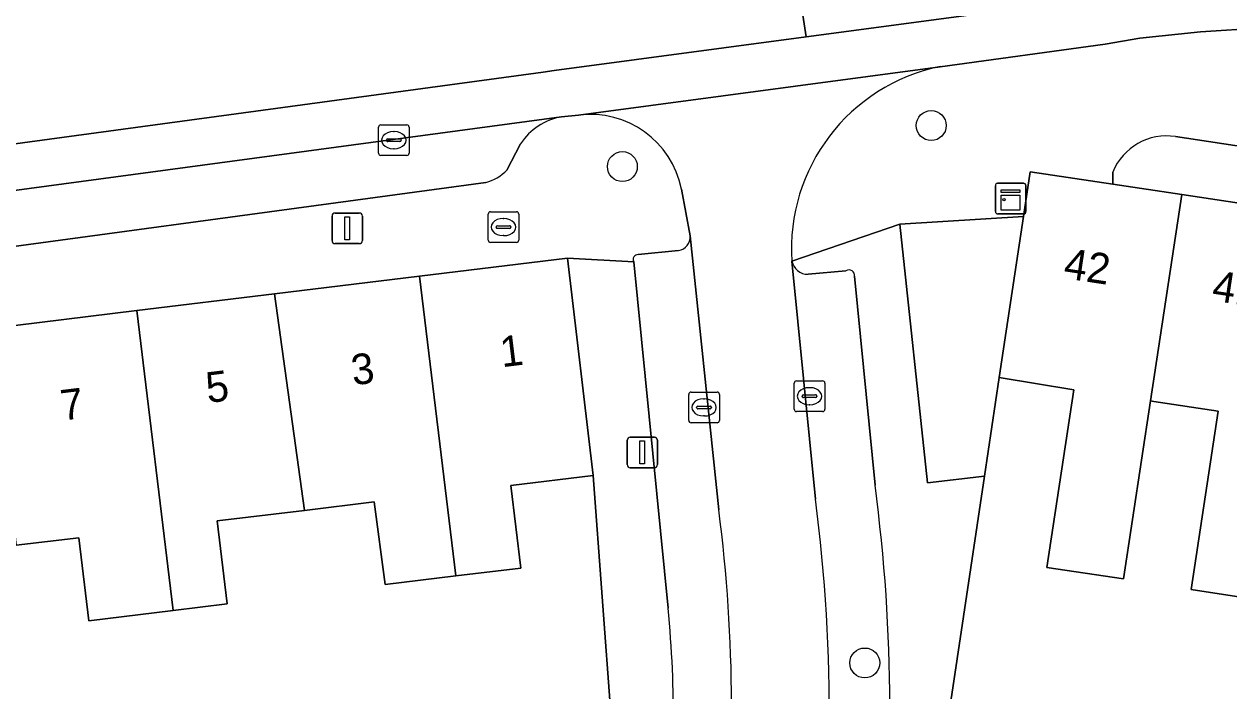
# Model space of a CAD drawing. Extents: x 162172 to 163187, y 382874 to 383685.
# Drawn here: x 162894.52 to 162933.89, y 383259.09 to 383280.9 of the extents above; entities that cross this region are included whole.
import ezdxf

# ---------------------------------------------------------------- set-up
doc = ezdxf.new("R2010")
doc.units = 0
for name, color, linetype in [('IMGEO_Boom', 7, 'Continuous'), ('IMGEO_Brandkraan', 7, 'Continuous'), ('IMGEO_Erf', 7, 'Continuous'), ('IMGEO_Groenvoorziening', 7, 'Continuous'), ('IMGEO_Kast', 7, 'Continuous'), ('IMGEO_Kolk', 7, 'Continuous'), ('IMGEO_Lichtmast', 7, 'Continuous'), ('IMGEO_Muur', 7, 'Continuous'), ('IMGEO_Pand', 7, 'Continuous'), ('IMGEO_Pand_nummerreeks', 7, 'Continuous'), ('IMGEO_Parkeervlak_open', 7, 'Continuous'), ('IMGEO_Rijbaan_lokaal_gesloten', 7, 'Continuous'), ('IMGEO_Rijbaan_lokaal_open', 7, 'Continuous'), ('IMGEO_Voetpad_open', 7, 'Continuous')]:
    doc.layers.add(name, color=color, linetype=linetype)

msp = doc.modelspace()

# ---------------------------------------------------------------- linework, layer by layer
at = {"layer": 'IMGEO_Boom'}
for centre in [(162924.163, 383277.577), (162914.07, 383276.235), (162921.991, 383260.003)]:
    msp.add_circle(centre, 0.489, dxfattribs=at)
at = {"layer": 'IMGEO_Brandkraan'}
for p, q in [((162909.759, 383274.758), (162910.611, 383274.758)), ((162909.684, 383273.832), (162909.684, 383274.684)), ((162910.172, 383274.538), (162910.197, 383274.538)), ((162910.685, 383274.684), (162910.685, 383273.832)), ((162909.943, 383274.252), (162909.943, 383274.264)), ((162910.381, 383274.215), (162909.983, 383274.215)), ((162909.986, 383274.301), (162910.384, 383274.301)), ((162910.195, 383273.978), (162910.17, 383273.978)), ((162910.427, 383274.264), (162910.427, 383274.252)), ((162910.611, 383273.758), (162909.759, 383273.758))]:
    msp.add_line(p, q, dxfattribs=at)
for points in [[(162909.759, 383274.758), (162910.611, 383274.758)], [(162909.684, 383273.832), (162909.684, 383274.684)], [(162910.685, 383274.684), (162910.685, 383273.832)], [(162910.611, 383273.758), (162909.759, 383273.758)]]:
    msp.add_lwpolyline(points, dxfattribs=at)
for centre, radius, start, end in [((162909.761, 383274.682), 0.0765, 91.552, 178.448), ((162909.761, 383274.682), 0.0765, 91.552, 178.448), ((162910.609, 383274.682), 0.0765, 1.552, 88.448), ((162910.609, 383274.682), 0.0765, 1.552, 88.448), ((162909.983, 383274.261), 0.0403, 85.8775, 175.7526), ((162909.98, 383274.251), 0.0366, 178.938, 274.7102), ((162910.384, 383274.258), 0.043, 264.8664, 352.4533), ((162910.388, 383274.263), 0.0386, 1.7309, 96.639), ((162909.761, 383273.834), 0.0765, 181.552, 268.448), ((162909.761, 383273.834), 0.0765, 181.552, 268.448), ((162910.609, 383273.834), 0.0765, 271.552, 358.448), ((162910.609, 383273.834), 0.0765, 271.552, 358.448)]:
    msp.add_arc(centre, radius, start, end, dxfattribs=at)
for centre, major_axis, ratio, start_param, end_param in [((162910.171, 383274.258), (-0.387, 0.002), 0.722429, 4.712389, 7.853982), ((162910.196, 383274.258), (-0.39, 0.002), 0.717154, 1.570796, 4.712389)]:
    msp.add_ellipse(centre, major_axis=major_axis, ratio=ratio, start_param=start_param, end_param=end_param, dxfattribs=at)
at = {"layer": 'IMGEO_Erf'}
for points in [[(162978.626, 383270.167), (162932.146, 383277.218)], [(162930.093, 383276.055), (162930.093, 383275.66), (162932.35, 383275.32), (162936.892, 383274.636), (162941.594, 383273.928), (162946.296, 383273.22), (162950.997, 383272.512), (162955.7, 383271.804), (162960.402, 383271.096), (162965.104, 383270.388), (162969.805, 383269.68), (162974.508, 383268.972), (162979.454, 383268.227), (162979.583, 383269.208)], [(162934.989, 383262.05), (162932.66, 383262.403), (162933.544, 383268.238), (162931.436, 383268.558), (162931.329, 383268.574), (162930.448, 383262.75), (162927.945, 383263.13), (162928.827, 383268.939), (162926.38, 383269.333), (162925.9, 383266.108), (162923.881, 383252.56), (162927.616, 383251.955), (162927.192, 383249.152), (162928.361, 383248.961), (162928.518, 383250), (162928.785, 383251.765), (162932.219, 383251.209), (162932.041, 383250), (162931.805, 383248.398), (162934.581, 383247.955)], [(162894.504, 383252.462), (162896.421, 383252.512), (162896.387, 383255.35), (162899.825, 383255.537), (162903.59, 383255.742), (162903.622, 383253.045), (162906.327, 383252.747), (162906.744, 383255.382), (162910.388, 383254.806), (162914.003, 383254.234), (162913.119, 383266.134), (162910.43, 383265.808), (162910.757, 383263.107), (162908.624, 383262.849), (162906.315, 383262.569), (162905.961, 383265.268), (162903.681, 383264.992), (162900.827, 383264.647), (162901.156, 383261.937), (162899.391, 383261.721), (162896.633, 383261.383), (162896.303, 383264.098), (162894.263, 383263.851)]]:
    msp.add_lwpolyline(points, dxfattribs=at)
msp.add_arc((162931.858, 383275.332), 1.907, 81.3219, 157.7401, dxfattribs=at)
at = {"layer": 'IMGEO_Groenvoorziening'}
msp.add_lwpolyline([(162927.178, 383274.605), (162923.136, 383274.356), (162924.036, 383265.899), (162925.9, 383266.108), (162926.38, 383269.333)], close=True, dxfattribs=at)
at = {"layer": 'IMGEO_Kast'}
for p, q in [((162926.258, 383274.763), (162926.258, 383275.604)), ((162926.258, 383275.604), (162926.258, 383274.763)), ((162926.333, 383275.688), (162927.174, 383275.688)), ((162927.174, 383275.688), (162926.333, 383275.688)), ((162927.258, 383275.613), (162927.258, 383274.772)), ((162927.258, 383274.772), (162927.258, 383275.613)), ((162927.183, 383274.688), (162926.342, 383274.688)), ((162926.342, 383274.688), (162927.183, 383274.688))]:
    msp.add_line(p, q, dxfattribs=at)
for points in [[(162926.453, 383275.478), (162927.053, 383275.478), (162927.053, 383275.393), (162926.453, 383275.393), (162926.453, 383275.478)], [(162926.453, 383275.303), (162927.053, 383275.303), (162927.053, 383274.814), (162926.453, 383274.814), (162926.453, 383275.303)]]:
    msp.add_lwpolyline(points, dxfattribs=at)
msp.add_circle((162926.537, 383275.152), 0.0377, dxfattribs=at)
for centre, start, end in [((162926.336, 383275.61), 92.4484, 184.2845), ((162926.336, 383275.61), 92.4484, 184.2845), ((162927.18, 383275.61), 2.4484, 94.2845), ((162927.18, 383275.61), 2.4484, 94.2845), ((162926.336, 383274.766), 182.4484, 274.2845), ((162926.336, 383274.766), 182.4484, 274.2845), ((162927.18, 383274.766), 272.4484, 4.2845), ((162927.18, 383274.766), 272.4484, 4.2845)]:
    msp.add_arc(centre, 0.0779, start, end, dxfattribs=at)
at = {"layer": 'IMGEO_Kolk'}
for p, q in [((162906.102, 383276.675), (162906.102, 383277.527)), ((162906.177, 383277.601), (162907.029, 383277.601)), ((162907.103, 383277.527), (162907.103, 383276.675)), ((162906.361, 383277.095), (162906.361, 383277.107)), ((162906.404, 383277.144), (162906.802, 383277.144)), ((162906.59, 383277.381), (162906.615, 383277.381)), ((162906.845, 383277.107), (162906.845, 383277.095)), ((162906.799, 383277.058), (162906.401, 383277.058)), ((162906.613, 383276.821), (162906.588, 383276.821)), ((162907.029, 383276.601), (162906.177, 383276.601)), ((162919.761, 383269.226), (162920.613, 383269.226)), ((162916.313, 383268.86), (162917.165, 383268.86)), ((162919.686, 383268.3), (162919.686, 383269.152)), ((162920.174, 383269.006), (162920.199, 383269.006)), ((162920.687, 383269.152), (162920.687, 383268.3)), ((162916.238, 383267.934), (162916.238, 383268.786)), ((162916.726, 383268.64), (162916.751, 383268.64)), ((162917.239, 383268.786), (162917.239, 383267.934)), ((162919.945, 383268.72), (162919.945, 383268.732)), ((162920.383, 383268.683), (162919.985, 383268.683)), ((162919.988, 383268.769), (162920.386, 383268.769)), ((162920.197, 383268.446), (162920.172, 383268.446)), ((162920.429, 383268.732), (162920.429, 383268.72)), ((162916.497, 383268.354), (162916.497, 383268.366)), ((162916.935, 383268.317), (162916.537, 383268.317)), ((162916.54, 383268.403), (162916.938, 383268.403)), ((162916.749, 383268.08), (162916.724, 383268.08)), ((162916.981, 383268.366), (162916.981, 383268.354)), ((162920.613, 383268.226), (162919.761, 383268.226)), ((162917.165, 383267.86), (162916.313, 383267.86))]:
    msp.add_line(p, q, dxfattribs=at)
for points in [[(162906.102, 383276.675), (162906.102, 383277.527)], [(162906.177, 383277.601), (162907.029, 383277.601)], [(162907.103, 383277.527), (162907.103, 383276.675)], [(162907.029, 383276.601), (162906.177, 383276.601)], [(162919.761, 383269.226), (162920.613, 383269.226)], [(162916.313, 383268.86), (162917.165, 383268.86)], [(162919.686, 383268.3), (162919.686, 383269.152)], [(162920.687, 383269.152), (162920.687, 383268.3)], [(162916.238, 383267.934), (162916.238, 383268.786)], [(162917.239, 383268.786), (162917.239, 383267.934)], [(162920.613, 383268.226), (162919.761, 383268.226)], [(162917.165, 383267.86), (162916.313, 383267.86)]]:
    msp.add_lwpolyline(points, dxfattribs=at)
for centre, radius, start, end in [((162906.179, 383277.525), 0.0765, 91.552, 178.448), ((162906.179, 383277.525), 0.0765, 91.552, 178.448), ((162907.027, 383277.525), 0.0765, 1.552, 88.448), ((162907.027, 383277.525), 0.0765, 1.552, 88.448), ((162906.401, 383277.104), 0.0403, 85.8775, 175.7526), ((162906.398, 383277.094), 0.0366, 178.938, 274.7102), ((162906.802, 383277.101), 0.043, 264.8664, 352.4533), ((162906.806, 383277.106), 0.0386, 1.7309, 96.639), ((162906.179, 383276.677), 0.0765, 181.552, 268.448), ((162906.179, 383276.677), 0.0765, 181.552, 268.448), ((162907.027, 383276.677), 0.0765, 271.552, 358.448), ((162907.027, 383276.677), 0.0765, 271.552, 358.448), ((162919.763, 383269.15), 0.0765, 91.552, 178.448), ((162919.763, 383269.15), 0.0765, 91.552, 178.448), ((162920.611, 383269.15), 0.0765, 1.552, 88.448), ((162920.611, 383269.15), 0.0765, 1.552, 88.448), ((162916.315, 383268.784), 0.0765, 91.552, 178.448), ((162916.315, 383268.784), 0.0765, 91.552, 178.448), ((162917.163, 383268.784), 0.0765, 1.552, 88.448), ((162917.163, 383268.784), 0.0765, 1.552, 88.448), ((162919.985, 383268.729), 0.0403, 85.8775, 175.7526), ((162919.982, 383268.719), 0.0366, 178.938, 274.7102), ((162920.386, 383268.726), 0.043, 264.8664, 352.4533), ((162920.39, 383268.731), 0.0386, 1.7309, 96.639), ((162916.537, 383268.363), 0.0403, 85.8775, 175.7526), ((162916.534, 383268.353), 0.0366, 178.938, 274.7102), ((162916.938, 383268.36), 0.043, 264.8664, 352.4533), ((162916.942, 383268.365), 0.0386, 1.7309, 96.639), ((162919.763, 383268.302), 0.0765, 181.552, 268.448), ((162919.763, 383268.302), 0.0765, 181.552, 268.448), ((162920.611, 383268.302), 0.0765, 271.552, 358.448), ((162920.611, 383268.302), 0.0765, 271.552, 358.448), ((162916.315, 383267.936), 0.0765, 181.552, 268.448), ((162916.315, 383267.936), 0.0765, 181.552, 268.448), ((162917.163, 383267.936), 0.0765, 271.552, 358.448), ((162917.163, 383267.936), 0.0765, 271.552, 358.448)]:
    msp.add_arc(centre, radius, start, end, dxfattribs=at)
for centre, major_axis, ratio, start_param, end_param in [((162906.589, 383277.101), (-0.387, 0.002), 0.722429, 4.712389, 7.853982), ((162906.614, 383277.101), (-0.39, 0.002), 0.717154, 1.570796, 4.712389), ((162920.173, 383268.726), (-0.387, 0.002), 0.722429, 4.712389, 7.853982), ((162920.198, 383268.726), (-0.39, 0.002), 0.717154, 1.570796, 4.712389), ((162916.725, 383268.36), (-0.387, 0.002), 0.722429, 4.712389, 7.853982), ((162916.75, 383268.36), (-0.39, 0.002), 0.717154, 1.570796, 4.712389)]:
    msp.add_ellipse(centre, major_axis=major_axis, ratio=ratio, start_param=start_param, end_param=end_param, dxfattribs=at)
at = {"layer": 'IMGEO_Lichtmast'}
for p, q in [((162904.584, 383273.815), (162904.584, 383274.615)), ((162904.584, 383274.615), (162904.584, 383273.815)), ((162904.684, 383274.715), (162905.474, 383274.715)), ((162905.474, 383274.715), (162904.684, 383274.715)), ((162905.574, 383274.615), (162905.574, 383273.815)), ((162905.574, 383273.815), (162905.574, 383274.615)), ((162905.474, 383273.715), (162904.684, 383273.715)), ((162904.684, 383273.715), (162905.474, 383273.715)), ((162914.226, 383266.488), (162914.226, 383267.288)), ((162914.226, 383267.288), (162914.226, 383266.488)), ((162914.326, 383267.388), (162915.116, 383267.388)), ((162915.116, 383267.388), (162914.326, 383267.388)), ((162915.216, 383267.288), (162915.216, 383266.488)), ((162915.216, 383266.488), (162915.216, 383267.288)), ((162915.116, 383266.388), (162914.326, 383266.388)), ((162914.326, 383266.388), (162915.116, 383266.388))]:
    msp.add_line(p, q, dxfattribs=at)
for points in [[(162905.004, 383274.59), (162905.154, 383274.59), (162905.154, 383273.84), (162905.004, 383273.84), (162905.004, 383274.59)], [(162914.646, 383267.263), (162914.796, 383267.263), (162914.796, 383266.513), (162914.646, 383266.513), (162914.646, 383267.263)]]:
    msp.add_lwpolyline(points, dxfattribs=at)
for centre, start, end in [((162904.684, 383274.615), 90, 180), ((162904.684, 383274.615), 90, 180), ((162905.474, 383274.615), 0, 90), ((162905.474, 383274.615), 360, 90), ((162904.684, 383273.815), 180, 270), ((162904.684, 383273.815), 180, 270), ((162905.474, 383273.815), 270, 0), ((162905.474, 383273.815), 270, 0), ((162914.326, 383267.288), 90, 180), ((162914.326, 383267.288), 90, 180), ((162915.116, 383267.288), 0, 90), ((162915.116, 383267.288), 360, 90), ((162914.326, 383266.488), 180, 270), ((162914.326, 383266.488), 180, 270), ((162915.116, 383266.488), 270, 0), ((162915.116, 383266.488), 270, 0)]:
    msp.add_arc(centre, 0.1, start, end, dxfattribs=at)
at = {"layer": 'IMGEO_Muur'}
for points in [[(162926.38, 383269.333), (162925.9, 383266.108)], [(162925.9, 383266.108), (162923.881, 383252.56)]]:
    msp.add_lwpolyline(points, dxfattribs=at)
at = {"layer": 'IMGEO_Pand'}
for points in [[(162932.35, 383275.32), (162930.093, 383275.66), (162927.399, 383276.066), (162927.178, 383274.605), (162926.38, 383269.333), (162928.827, 383268.939), (162927.945, 383263.13), (162930.448, 383262.75), (162931.329, 383268.574)], [(162936.892, 383274.636), (162932.35, 383275.32), (162931.329, 383268.574), (162931.436, 383268.558), (162933.544, 383268.238), (162932.66, 383262.403), (162934.989, 383262.05)], [(162907.437, 383272.649), (162908.624, 383262.849), (162910.757, 383263.107), (162910.43, 383265.808), (162913.119, 383266.134), (162912.274, 383273.237)], [(162903.681, 383264.992), (162905.961, 383265.268), (162906.315, 383262.569), (162908.624, 383262.849), (162907.437, 383272.649), (162902.7, 383272.072)], [(162902.7, 383272.072), (162898.204, 383271.525), (162899.391, 383261.721), (162901.156, 383261.937), (162900.827, 383264.647), (162903.681, 383264.992)], [(162894.263, 383263.851), (162896.303, 383264.098), (162896.633, 383261.383), (162899.391, 383261.721), (162898.204, 383271.525), (162893.42, 383270.943)]]:
    msp.add_lwpolyline(points, close=True, dxfattribs=at)
at = {"layer": 'IMGEO_Parkeervlak_open'}
for points in [[(162912.085, 383277.862), (162862.712, 383271.218)], [(162910.298, 383276.119), (162910.744, 383276.984)], [(162865.608, 383269.734), (162868.141, 383270.092), (162909.604, 383275.716)], [(162917.22, 383265.009), (162916.284, 383273.966)], [(162915.906, 383273.488), (162914.591, 383273.358)], [(162919.612, 383273.145), (162920.38, 383265.363)], [(162914.441, 383273.117), (162915.566, 383261.8)], [(162921.377, 383272.83), (162920.139, 383272.713)], [(162922.327, 383265.813), (162921.66, 383272.649)]]:
    msp.add_lwpolyline(points, dxfattribs=at)
for centre, radius, start, end in [((162912.426, 383275.878), 2.013, 99.7533, 146.6751), ((162909.225, 383277.168), 1.501, 284.6361, 315.6506), ((162915.818, 383273.946), 0.467, 280.8921, 2.4344), ((162914.581, 383273.197), 0.161, 86.4825, 209.7207), ((162920.137, 383273.248), 0.535, 191.0764, 270.2383), ((162921.474, 383272.669), 0.188, 353.7918, 121.0042), ((162867.05, 383258.465), 55.763, 352.771, 7.572), ((162867.914, 383258.475), 52.916, 351.0713, 7.4794), ((162867.382, 383258.547), 50.256, 352.911, 7.3876), ((162876.654, 383258.105), 39.087, 353.7542, 5.4239)]:
    msp.add_arc(centre, radius, start, end, dxfattribs=at)
at = {"layer": 'IMGEO_Rijbaan_lokaal_gesloten'}
for points in [[(162746.988, 383284.773), (162754.973, 383275.848), (162761.671, 383268.445), (162764.865, 383265.64), (162770.006, 383263.146), (162774.835, 383262.367), (162778.262, 383262.289), (162808.407, 383266.029), (162835.747, 383269.38), (162863.477, 383272.809), (162911.477, 383279.327), (162911.844, 383279.376), (162920.076, 383280.478), (162919.326, 383285.358)], [(162919.326, 383285.358), (162920.076, 383280.478), (162927.187, 383281.43)], [(162927.187, 383281.43), (162920.076, 383280.478), (162911.844, 383279.376), (162911.477, 383279.327), (162863.477, 383272.809), (162835.747, 383269.38), (162808.407, 383266.029), (162778.262, 383262.289), (162774.835, 383262.367), (162770.006, 383263.146), (162764.865, 383265.64), (162761.671, 383268.445), (162754.973, 383275.848), (162746.988, 383284.773)], [(162775.63, 383260.847), (162781.571, 383261.396), (162786.414, 383262.022), (162787.483, 383262.198), (162790.095, 383262.473), (162819.027, 383265.957), (162822.009, 383266.344), (162848.142, 383269.478), (162851.329, 383269.83), (162862.219, 383271.142), (162862.712, 383271.218), (162912.085, 383277.862), (162912.638, 383277.916), (162924.452, 383279.503), (162929.847, 383280.24), (162930.976, 383280.432), (162932.962, 383280.637), (162934.995, 383280.773)]]:
    msp.add_lwpolyline(points, dxfattribs=at)
at = {"layer": 'IMGEO_Rijbaan_lokaal_open'}
for points in [[(162924.452, 383279.503), (162912.638, 383277.916)], [(162916.003, 383275.501), (162916.284, 383273.966), (162917.22, 383265.009)], [(162920.38, 383265.363), (162919.612, 383273.145)]]:
    msp.add_lwpolyline(points, dxfattribs=at)
for centre, radius, start, end in [((162925.674, 383273.552), 6.076, 101.6027, 183.8372), ((162913.025, 383274.903), 3.037, 11.3477, 97.3197), ((162867.914, 383258.475), 52.916, 351.0713, 7.4794), ((162867.382, 383258.547), 50.256, 352.911, 7.3876)]:
    msp.add_arc(centre, radius, start, end, dxfattribs=at)
at = {"layer": 'IMGEO_Voetpad_open'}
for points in [[(162935.314, 383280.725), (162934.995, 383280.773), (162932.962, 383280.637), (162930.976, 383280.432), (162929.847, 383280.24), (162924.452, 383279.503)], [(162912.638, 383277.916), (162912.085, 383277.862)], [(162932.146, 383277.218), (162978.626, 383270.167)], [(162910.744, 383276.984), (162910.298, 383276.119)], [(162919.612, 383273.145), (162923.136, 383274.356), (162927.178, 383274.605), (162927.399, 383276.066), (162930.093, 383275.66), (162930.093, 383276.055)], [(162909.604, 383275.716), (162868.141, 383270.092), (162865.608, 383269.734)], [(162916.284, 383273.966), (162916.003, 383275.501)], [(162909.545, 383157.158), (162909.977, 383160.133), (162910.196, 383161.591), (162916.594, 383204.144), (162916.805, 383205.549), (162923.232, 383248.295), (162923.453, 383249.764), (162923.881, 383252.56), (162925.9, 383266.108), (162924.036, 383265.899), (162923.136, 383274.356), (162919.612, 383273.145)], [(162893.42, 383270.943), (162898.204, 383271.525), (162902.7, 383272.072), (162907.437, 383272.649), (162912.274, 383273.237), (162914.441, 383273.117)], [(162915.566, 383261.8), (162914.441, 383273.117), (162912.274, 383273.237), (162913.119, 383266.134), (162914.003, 383254.234), (162913.526, 383251.254), (162913.333, 383250), (162913.302, 383249.799), (162906.731, 383207.017), (162906.539, 383205.766), (162906.505, 383205.532), (162900.276, 383163.119), (162900.06, 383161.648), (162900.192, 383161.628), (162899.697, 383158.408), (162898.651, 383153.856), (162897.653, 383149.297), (162895.206, 383138.052), (162894.584, 383138.19), (162894.525, 383137.704)], [(162914.591, 383273.358), (162915.906, 383273.488)], [(162920.139, 383272.713), (162921.377, 383272.83)], [(162921.66, 383272.649), (162922.327, 383265.813)]]:
    msp.add_lwpolyline(points, dxfattribs=at)
for centre, radius, start, end in [((162925.674, 383273.552), 6.076, 101.6027, 183.8372), ((162913.025, 383274.903), 3.037, 11.3477, 97.3197), ((162912.426, 383275.878), 2.013, 99.7533, 146.6751), ((162931.858, 383275.332), 1.907, 81.3219, 157.7401), ((162909.225, 383277.168), 1.501, 284.6361, 315.6506), ((162915.818, 383273.946), 0.467, 280.8921, 2.4344), ((162914.581, 383273.197), 0.161, 86.4825, 209.7207), ((162920.137, 383273.248), 0.535, 191.0764, 270.2383), ((162921.474, 383272.669), 0.188, 353.7918, 121.0042), ((162867.05, 383258.465), 55.763, 352.771, 7.572), ((162876.654, 383258.105), 39.087, 353.7542, 5.4239)]:
    msp.add_arc(centre, radius, start, end, dxfattribs=at)

# ---------------------------------------------------------------- texts
at = {"layer": 'IMGEO_Pand_nummerreeks'}
for s, rotation, p in [('42', 351.4343, (162928.456, 383272.59)), ('41', 351.4343, (162933.304, 383271.86)), ('1', 6.9358, (162910.135, 383269.672)), ('3', 6.9358, (162905.271, 383269.081)), ('5', 6.9385, (162900.521, 383268.503)), ('7', 6.9358, (162895.77, 383267.926))]:
    msp.add_text(s, height=1, rotation=rotation, dxfattribs=at).set_placement(p)

doc.saveas('drawing.dxf')
